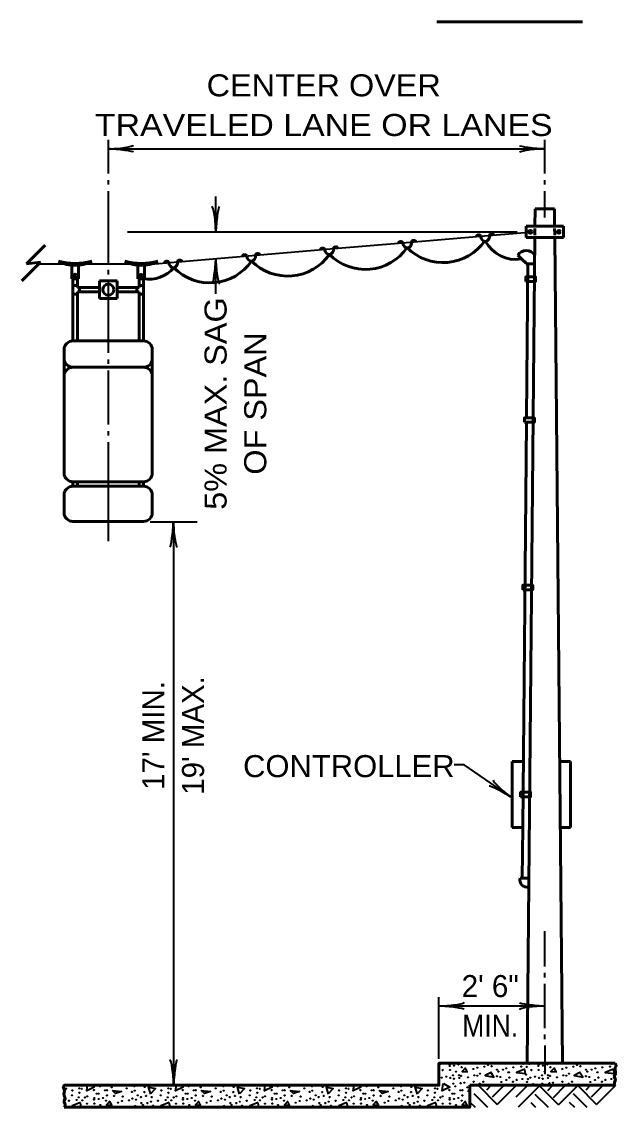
# Model space of a CAD drawing. Extents: x -1 to 679, y 1 to 441.
# Drawn here: x 308.1 to 375.5, y 100.6 to 223.8 of the extents above; entities that cross this region are included whole.
import ezdxf
from ezdxf.enums import TextEntityAlignment as Align

# ---------------------------------------------------------------- set-up
doc = ezdxf.new("R2010")
doc.units = 0
doc.layers.add('1', color=7, linetype='Continuous', lineweight=35)

msp = doc.modelspace()

# ---------------------------------------------------------------- hatches: boundary and pattern name
at = {"layer": '1'}
for points in [[(365.932, 199.947, 1), (365.608, 199.947, 1)], [(369.173, 199.947, 1), (368.85, 199.947, 1)], [(314.264, 194.997, 1), (314.014, 194.997, 1)], [(321.766, 194.994, 1), (321.516, 194.994, 1)]]:
    msp.add_hatch(color=256, dxfattribs=at).paths.add_polyline_path(points)

# ---------------------------------------------------------------- linework, layer by layer
at = {"layer": '1', "lineweight": 53}
for p, q in [((371.671, 223.796), (355.171, 223.796)), ((366.303, 202.57), (366.285, 200.57)), ((366.304, 202.57), (368.507, 202.57)), ((368.507, 202.57), (368.526, 200.57)), ((365.285, 200.57), (369.526, 200.57)), ((365.285, 200.57), (365.285, 199.32)), ((366.283, 200.32), (366.276, 199.57)), ((368.528, 200.32), (368.535, 199.57)), ((369.526, 200.57), (369.526, 199.32)), ((308.617, 196.302), (310.739, 198.423)), ((365.285, 199.32), (369.526, 199.32)), ((366.273, 199.32), (365.405, 105.57)), ((368.537, 199.32), (369.406, 105.57)), ((365.056, 196.578), (364.349, 197.285)), ((308.084, 194.376), (310.206, 196.497)), ((308.617, 196.302), (310.206, 196.497)), ((313.767, 194.619), (313.767, 196.119)), ((314.517, 194.619), (314.517, 196.119)), ((321.267, 194.619), (321.267, 196.119)), ((322.017, 194.619), (322.017, 196.119)), ((366.246, 196.32), (365.246, 196.32)), ((365.496, 196.32), (365.333, 178.827)), ((313.767, 194.619), (314.517, 194.619)), ((313.892, 194.619), (313.892, 187.57)), ((314.392, 193.869), (313.892, 193.869)), ((314.392, 193.619), (314.392, 194.619)), ((316.892, 193.619), (314.392, 193.619)), ((314.642, 193.619), (314.642, 193.119)), ((316.892, 194.369), (318.892, 194.369)), ((316.892, 194.369), (316.892, 192.369)), ((318.892, 194.369), (318.892, 192.369)), ((318.892, 193.619), (321.392, 193.619)), ((321.142, 193.619), (321.142, 193.119)), ((321.267, 194.619), (322.017, 194.619)), ((321.392, 193.619), (321.392, 194.619)), ((321.392, 193.869), (321.892, 193.869)), ((321.892, 194.619), (321.892, 187.57)), ((314.392, 192.869), (313.892, 192.869)), ((316.892, 193.119), (314.392, 193.119)), ((314.392, 193.119), (314.392, 187.57)), ((316.892, 192.369), (318.892, 192.369)), ((318.892, 193.119), (321.392, 193.119)), ((321.392, 193.119), (321.392, 187.57)), ((321.392, 192.869), (321.892, 192.869)), ((313.892, 187.57), (321.892, 187.57)), ((312.892, 186.57), (312.892, 172.57)), ((322.892, 186.57), (322.892, 172.57)), ((313.892, 184.57), (321.892, 184.57)), ((365.329, 178.321), (364.903, 132.329)), ((313.892, 171.57), (321.892, 171.57)), ((313.892, 171.57), (313.892, 171.07)), ((314.392, 171.57), (314.392, 171.07)), ((321.392, 171.57), (321.392, 171.07)), ((321.892, 171.57), (321.892, 171.07)), ((312.892, 170.07), (312.892, 168.07)), ((313.892, 171.07), (321.892, 171.07)), ((322.892, 170.07), (322.892, 168.07)), ((313.892, 167.07), (321.892, 167.07)), ((363.722, 139.823), (363.722, 132.329)), ((364.972, 139.823), (363.722, 139.823)), ((370.338, 139.823), (369.088, 139.823)), ((370.338, 139.823), (370.338, 132.329)), ((364.903, 132.329), (363.722, 132.329)), ((364.903, 132.329), (364.85, 126.569)), ((370.338, 132.329), (369.158, 132.329)), ((365.6, 126.569), (364.6, 126.569)), ((375.405, 103.07), (358.905, 103.07))]:
    msp.add_line(p, q, dxfattribs=at)
at = {"layer": '1'}
for p, q in [((317.892, 210.369), (317.892, 206.57)), ((367.405, 206.57), (367.405, 210.369)), ((317.892, 209.369), (367.405, 209.369)), ((317.892, 205.82), (317.892, 205.32)), ((367.405, 205.32), (367.405, 205.82)), ((317.892, 204.57), (317.892, 196.369)), ((367.405, 201.57), (367.405, 204.57)), ((330.094, 199.945), (330.094, 203.945)), ((320.094, 199.945), (364.285, 199.945)), ((359.645, 199.399), (365.615, 199.902)), ((343.949, 198.075), (350.801, 198.653)), ((350.798, 198.653), (359.645, 199.398)), ((326.254, 196.584), (335.1, 197.33)), ((335.1, 197.33), (343.949, 198.076)), ((313.018, 196.29), (309.999, 196.29)), ((320.518, 196.29), (315.265, 196.29)), ((322.764, 196.29), (326.254, 196.584)), ((330.094, 192.908), (330.094, 196.908)), ((317.892, 195.619), (317.892, 195.119)), ((317.892, 191.369), (317.892, 186.22)), ((317.892, 185.47), (317.892, 184.97)), ((317.892, 184.22), (317.892, 179.07)), ((317.892, 179.07), (317.892, 178.07)), ((317.892, 177.32), (317.892, 176.82)), ((317.892, 176.07), (317.892, 164.815)), ((322.642, 167.032), (327.995, 167.032)), ((325.3, 167.032), (325.3, 103.07)), ((367.405, 116.57), (367.405, 120.57)), ((367.405, 115.32), (367.405, 115.82)), ((367.405, 109.57), (367.405, 114.57)), ((355.405, 106.07), (355.405, 113.07)), ((355.405, 112.07), (367.405, 112.07)), ((367.405, 108.32), (367.405, 108.82)), ((367.405, 107.57), (367.405, 104.32)), ((358.693, 102.487), (358.905, 102.462)), ((358.905, 102.274), (358.693, 102.487)), ((359.885, 103.031), (362.025, 100.891)), ((361.305, 103.031), (360.786, 102.51)), ((362.745, 103.031), (361.425, 101.71)), ((364.166, 103.031), (362.025, 100.891)), ((365.445, 103.031), (364.125, 101.71)), ((366.865, 103.031), (364.405, 100.57)), ((365.942, 103.07), (365.973, 103.287)), ((366.013, 103.267), (366.356, 103.07)), ((366.765, 103.031), (368.965, 100.831)), ((368.286, 103.031), (367.726, 102.45)), ((369.726, 103.031), (368.346, 101.65)), ((371.145, 103.031), (368.965, 100.831)), ((371.145, 103.031), (373.286, 100.891)), ((372.565, 103.031), (372.046, 102.51)), ((374.005, 103.031), (372.685, 101.71)), ((375.425, 103.031), (373.286, 100.891)), ((358.905, 101.17), (359.505, 100.57)), ((359.365, 102.13), (360.925, 100.57)), ((365.825, 101.111), (366.365, 100.57)), ((366.286, 102.07), (367.802, 100.57)), ((370.166, 101.17), (370.765, 100.57)), ((370.625, 102.13), (372.185, 100.57)), ((320.993, 100.727), (320.707, 100.57)), ((321.066, 100.57), (320.953, 100.747)), ((331.073, 100.727), (330.787, 100.57)), ((331.146, 100.57), (331.033, 100.747)), ((341.153, 100.727), (340.867, 100.57)), ((341.226, 100.57), (341.113, 100.747)), ((351.233, 100.727), (350.947, 100.57)), ((351.306, 100.57), (351.193, 100.747))]:
    msp.add_line(p, q, dxfattribs=at)
at = {"layer": '1', "lineweight": 53}
for points in [[(365.246, 194.32), (365.246, 194.82), (366.371, 194.82), (366.371, 194.32)], [(365.102, 178.327), (365.102, 178.827), (366.227, 178.827), (366.227, 178.327)], [(364.911, 159.322), (364.911, 159.822), (366.036, 159.822), (366.036, 159.322)], [(364.669, 135.823), (364.669, 136.323), (365.794, 136.323), (365.794, 135.823)]]:
    msp.add_lwpolyline(points, close=True, dxfattribs=at)
at = {"layer": '1'}
for points in [[(317.892, 194.369), (317.892, 191.869), (317.892, 191.369)], [(363.703, 135.714), (358.28, 139.432), (357.127, 139.432)], [(358.413, 105.047), (358.033, 104.647), (358.613, 104.607), (358.413, 105.007)], [(365.133, 104.907), (364.193, 104.527), (365.233, 104.407), (365.133, 104.867)], [(368.493, 105.047), (368.113, 104.647), (368.693, 104.607), (368.493, 105.007)], [(375.213, 104.907), (374.273, 104.527), (375.313, 104.407), (375.213, 104.867)], [(361.313, 104.527), (360.653, 104.167), (361.633, 103.987), (361.273, 104.547)], [(371.393, 104.527), (370.733, 104.167), (371.713, 103.987), (371.353, 104.547)], [(312.795, 102.784), (313.173, 102.707), (312.923, 102.439)], [(315.957, 103.07), (316.313, 102.867), (315.453, 102.447), (315.542, 103.07)], [(322.713, 102.067), (322.473, 102.867), (323.253, 102.707), (322.693, 102.107)], [(326.036, 103.07), (326.393, 102.867), (325.533, 102.447), (325.622, 103.07)], [(332.793, 102.067), (332.553, 102.867), (333.333, 102.707), (332.773, 102.107)], [(336.116, 103.07), (336.473, 102.867), (335.613, 102.447), (335.702, 103.07)], [(342.873, 102.067), (342.633, 102.867), (343.413, 102.707), (342.853, 102.107)], [(346.197, 103.07), (346.553, 102.867), (345.693, 102.447), (345.782, 103.07)], [(352.953, 102.067), (352.713, 102.867), (353.493, 102.707), (352.933, 102.107)], [(355.933, 103.267), (356.633, 102.867), (355.773, 102.447), (355.893, 103.287)], [(314.733, 101.107), (313.793, 100.727), (314.833, 100.607), (314.733, 101.067)], [(318.093, 101.247), (317.713, 100.847), (318.293, 100.807), (318.093, 101.207)], [(324.813, 101.107), (323.873, 100.727), (324.913, 100.607), (324.813, 101.067)], [(328.173, 101.247), (327.793, 100.847), (328.373, 100.807), (328.173, 101.207)], [(334.893, 101.107), (333.953, 100.727), (334.993, 100.607), (334.893, 101.067)], [(338.253, 101.247), (337.873, 100.847), (338.453, 100.807), (338.253, 101.207)], [(344.973, 101.107), (344.033, 100.727), (345.073, 100.607), (344.973, 101.067)], [(348.333, 101.247), (347.953, 100.847), (348.533, 100.807), (348.333, 101.207)], [(355.053, 101.107), (354.113, 100.727), (355.153, 100.607), (355.053, 101.067)], [(358.413, 101.247), (358.033, 100.847), (358.613, 100.807), (358.413, 101.207)]]:
    msp.add_lwpolyline(points, dxfattribs=at)
at = {"layer": '1', "lineweight": 53}
for points in [[(312.906, 100.57), (312.996, 100.702), (313.002, 100.915), (312.893, 101.16), (312.909, 101.302), (313.024, 101.575), (312.898, 101.918), (312.871, 102.076), (312.925, 102.414), (312.909, 102.573), (312.795, 102.785), (312.906, 103.07), (355.405, 103.07), (355.405, 105.57), (375.405, 105.57)], [(375.405, 105.57), (375.516, 105.285), (375.402, 105.073), (375.385, 104.914), (375.44, 104.576), (375.413, 104.418), (375.287, 104.075), (375.402, 103.802), (375.418, 103.66), (375.309, 103.415), (375.315, 103.202), (375.405, 103.07)], [(358.905, 103.07), (358.905, 100.57), (312.906, 100.57)]]:
    msp.add_lwpolyline(points, dxfattribs=at)
at = {"layer": '1'}
for points in [[(318.373, 102.487), (319.413, 102.367), (318.733, 102.127)], [(328.453, 102.487), (329.493, 102.367), (328.813, 102.127)], [(338.533, 102.487), (339.573, 102.367), (338.893, 102.127)], [(348.613, 102.487), (349.653, 102.367), (348.973, 102.127)]]:
    msp.add_lwpolyline(points, close=True, dxfattribs=at)
at = {"layer": '1', "lineweight": 53}
for centre, radius in [((365.77, 199.947), 0.162), ((369.012, 199.947), 0.162), ((314.139, 194.997), 0.125), ((321.641, 194.994), 0.125), ((317.903, 193.379), 0.625)]:
    msp.add_circle(centre, radius, dxfattribs=at)
at = {"layer": '1'}
for centre in [(355.566, 105.484), (355.817, 104.786), (356.613, 105.25), (356.626, 105.417), (356.652, 104.799), (357.116, 105.303), (357.607, 105.431), (357.972, 105.117), (359.311, 104.905), (359.761, 105.077), (360.57, 105.17), (360.967, 105.364), (361.365, 105.237), (361.921, 105.523), (361.988, 104.839), (362.664, 104.839), (363.061, 104.998), (363.154, 105.523), (363.843, 105.104), (364.731, 105.197), (364.943, 105.51), (365.367, 105.157), (365.646, 105.484), (365.897, 104.786), (366.693, 105.25), (366.706, 105.417), (366.732, 104.799), (367.196, 105.303), (367.687, 105.431), (368.052, 105.117), (369.391, 104.905), (369.841, 105.077), (370.65, 105.17), (371.047, 105.364), (371.445, 105.237), (372.001, 105.523), (372.068, 104.839), (372.744, 104.839), (373.141, 104.998), (373.234, 105.523), (373.923, 105.104), (374.811, 105.197), (375.023, 105.51), (355.698, 103.937), (356.228, 104.057), (356.679, 103.911), (356.997, 104.202), (357.103, 103.805), (357.328, 104.613), (357.686, 104.216), (357.699, 103.898), (357.919, 104.136), (358.701, 103.964), (359.417, 104.189), (359.761, 104.149), (360.079, 104.388), (361.988, 104.096), (362.147, 104.627), (362.372, 104.004), (363.035, 103.672), (363.287, 104.534), (363.34, 104.534), (363.406, 103.951), (364.214, 103.685), (364.864, 103.778), (365.261, 104.269), (365.5, 103.765), (365.778, 103.937), (366.308, 104.057), (366.759, 103.911), (367.077, 104.202), (367.183, 103.805), (367.408, 104.613), (367.766, 104.216), (367.779, 103.898), (367.999, 104.136), (368.781, 103.964), (369.497, 104.189), (369.841, 104.149), (370.159, 104.388), (372.068, 104.096), (372.227, 104.627), (372.452, 104.004), (373.115, 103.672), (373.367, 104.534), (373.42, 104.534), (373.486, 103.951), (374.294, 103.685), (374.944, 103.778), (313.841, 102.479), (314.623, 102.731), (314.914, 102.665), (316.266, 102.519), (316.955, 102.956), (317.519, 102.49), (317.745, 102.506), (318.288, 102.837), (319.985, 102.731), (320.581, 102.32), (320.859, 102.956), (320.899, 102.466), (321.999, 102.293), (322.039, 102.89), (323.921, 102.479), (324.703, 102.731), (324.994, 102.665), (326.346, 102.519), (327.035, 102.956), (327.599, 102.49), (327.825, 102.506), (328.368, 102.837), (330.065, 102.731), (330.661, 102.32), (330.939, 102.956), (330.979, 102.466), (332.079, 102.293), (332.119, 102.89), (334.001, 102.479), (334.783, 102.731), (335.074, 102.665), (336.426, 102.519), (337.115, 102.956), (337.679, 102.49), (337.905, 102.506), (338.448, 102.837), (340.145, 102.731), (340.741, 102.32), (341.019, 102.956), (341.059, 102.466), (342.159, 102.293), (342.199, 102.89), (344.081, 102.479), (344.863, 102.731), (345.154, 102.665), (346.506, 102.519), (347.195, 102.956), (347.759, 102.49), (347.985, 102.506), (348.528, 102.837), (350.225, 102.731), (350.821, 102.32), (351.099, 102.956), (351.139, 102.466), (352.239, 102.293), (352.279, 102.89), (354.161, 102.479), (354.943, 102.731), (355.234, 102.665), (356.586, 102.519), (357.05, 103.248), (357.275, 102.956), (357.839, 102.49), (357.858, 103.301), (358.065, 102.506), (358.277, 103.354), (358.608, 102.837), (359.337, 103.46), (360.026, 103.248), (360.424, 103.46), (361.59, 103.129), (362.491, 103.434), (363.803, 103.46), (365.327, 103.142), (365.394, 103.447), (367.13, 103.248), (367.938, 103.301), (368.357, 103.354), (369.417, 103.46), (370.106, 103.248), (370.504, 103.46), (371.67, 103.129), (372.571, 103.434), (373.883, 103.46), (313.443, 101.304), (313.774, 101.935), (314.331, 101.397), (314.543, 101.71), (314.636, 102.214), (314.967, 101.357), (315.246, 101.684), (315.524, 101.803), (316.293, 101.45), (316.306, 101.617), (316.597, 102.121), (316.796, 101.503), (316.823, 102.121), (317.287, 101.631), (317.652, 101.317), (317.745, 101.909), (318.553, 101.869), (318.991, 101.105), (319.441, 101.277), (319.547, 101.79), (320.25, 101.37), (320.647, 101.564), (321.045, 101.437), (321.244, 101.922), (321.601, 101.723), (321.668, 101.039), (322.185, 101.869), (322.344, 101.039), (322.741, 101.198), (322.834, 101.723), (323.523, 101.304), (323.854, 101.935), (324.411, 101.397), (324.623, 101.71), (324.716, 102.214), (325.047, 101.357), (325.326, 101.684), (325.604, 101.803), (326.373, 101.45), (326.386, 101.617), (326.677, 102.121), (326.876, 101.503), (326.903, 102.121), (327.367, 101.631), (327.732, 101.317), (327.825, 101.909), (328.633, 101.869), (329.071, 101.105), (329.521, 101.277), (329.627, 101.79), (330.33, 101.37), (330.727, 101.564), (331.125, 101.437), (331.324, 101.922), (331.681, 101.723), (331.748, 101.039), (332.265, 101.869), (332.424, 101.039), (332.821, 101.198), (332.914, 101.723), (333.603, 101.304), (333.934, 101.935), (334.491, 101.397), (334.703, 101.71), (334.796, 102.214), (335.127, 101.357), (335.406, 101.684), (335.684, 101.803), (336.453, 101.45), (336.466, 101.617), (336.757, 102.121), (336.956, 101.503), (336.983, 102.121), (337.447, 101.631), (337.812, 101.317), (337.905, 101.909), (338.713, 101.869), (339.151, 101.105), (339.601, 101.277), (339.707, 101.79), (340.41, 101.37), (340.807, 101.564), (341.205, 101.437), (341.404, 101.922), (341.761, 101.723), (341.828, 101.039), (342.345, 101.869), (342.504, 101.039), (342.901, 101.198), (342.994, 101.723), (343.683, 101.304), (344.014, 101.935), (344.571, 101.397), (344.783, 101.71), (344.876, 102.214), (345.207, 101.357), (345.486, 101.684), (345.764, 101.803), (346.533, 101.45), (346.546, 101.617), (346.837, 102.121), (347.036, 101.503), (347.063, 102.121), (347.527, 101.631), (347.892, 101.317), (347.985, 101.909), (348.793, 101.869), (349.231, 101.105), (349.681, 101.277), (349.787, 101.79), (350.49, 101.37), (350.887, 101.564), (351.285, 101.437), (351.484, 101.922), (351.841, 101.723), (351.908, 101.039), (352.425, 101.869), (352.584, 101.039), (352.981, 101.198), (353.074, 101.723), (353.763, 101.304), (354.094, 101.935), (354.651, 101.397), (354.863, 101.71), (354.956, 102.214), (355.287, 101.357), (355.566, 101.684), (355.844, 101.803), (356.613, 101.45), (356.626, 101.617), (356.917, 102.121), (357.116, 101.503), (357.143, 102.121), (357.607, 101.631), (357.972, 101.317), (358.065, 101.909), (358.873, 101.869), (315.497, 100.986), (316.332, 100.999), (317.008, 100.813), (321.827, 100.827), (322.967, 100.734), (323.02, 100.734), (325.577, 100.986), (326.412, 100.999), (327.088, 100.813), (331.907, 100.827), (333.047, 100.734), (333.1, 100.734), (335.657, 100.986), (336.492, 100.999), (337.168, 100.813), (341.987, 100.827), (343.127, 100.734), (343.18, 100.734), (345.737, 100.986), (346.572, 100.999), (347.248, 100.813), (352.067, 100.827), (353.207, 100.734), (353.26, 100.734), (355.817, 100.986), (356.652, 100.999), (357.328, 100.813)]:
    msp.add_circle(centre, 0.0265, dxfattribs=at)
at = {"layer": '1', "lineweight": 53}
for centre, radius, start, end in [((361.397, 199.458), 0.267, 24.08975, 164.4687), ((351.056, 198.581), 0.267, 25.5313, 164.45861), ((355.885, 202.211), 5.764, 224.78783, 325.11132), ((352.55, 198.712), 0.267, 24.08975, 164.4687), ((359.903, 199.327), 0.267, 25.5313, 164.45861), ((364.057, 200.61), 3.789, 207.50003, 280.53329), ((333.362, 197.09), 0.267, 25.5313, 164.45861), ((338.247, 200.683), 5.764, 224.78783, 325.11132), ((334.857, 197.221), 0.267, 24.08975, 164.4687), ((342.211, 197.836), 0.267, 25.5313, 164.45861), ((347.066, 201.447), 5.764, 224.78783, 325.11132), ((343.705, 197.967), 0.267, 24.08975, 164.4687), ((365.311, 196.692), 1.131, 32.91213, 148.34152), ((314.142, 203.525), 7.156, 254.81071, 285.18929), ((314.142, 199.884), 3.766, 240.13717, 299.86284), ((321.642, 203.525), 7.156, 254.81071, 285.18929), ((321.642, 199.884), 3.766, 240.13717, 299.86284), ((324.516, 196.344), 0.267, 25.5313, 164.45861), ((329.428, 199.92), 5.764, 224.78783, 325.11132), ((326.011, 196.475), 0.267, 24.08975, 164.4687), ((365.047, 196.373), 0.205, 344.97633, 87.57779), ((322.502, 198.331), 3.762, 260.66909, 318.91993), ((313.892, 186.57), 1, 90, 180), ((321.892, 186.57), 1, 0, 90), ((313.892, 185.57), 1, 180, 270), ((321.892, 185.57), 1, 270, 0), ((313.892, 183.57), 1, 90, 180), ((321.892, 183.57), 1, 0, 90), ((313.892, 172.57), 1, 180, 270), ((321.892, 172.57), 1, 270, 0), ((313.892, 170.07), 1, 90, 180), ((321.892, 170.07), 1, 0, 90), ((313.892, 168.07), 1, 180, 270), ((321.892, 168.07), 1, 270, 0), ((365.396, 126.367), 0.821, 165.76102, 283.71131)]:
    msp.add_arc(centre, radius, start, end, dxfattribs=at)
at = {"layer": '1'}
for centre, start, end in [((359.867, 105.59), 226.35082, 313.64918), ((369.947, 105.59), 226.35082, 313.64918), ((375.447, 105.157), 61.61934, 241.7845), ((355.42, 103.765), 237.37076, 122.62924), ((375.341, 104.269), 32.83014, 287.06312), ((313.682, 103.089), 223.9797, 316.0203), ((314.199, 103.062), 162.01481, 17.98519), ((318.964, 103.062), 162.01481, 17.98519), ((323.762, 103.089), 223.9797, 316.0203), ((324.279, 103.062), 162.01481, 17.98519), ((329.044, 103.062), 162.01481, 17.98519), ((333.842, 103.089), 223.9797, 316.0203), ((334.359, 103.062), 162.01481, 17.98519), ((339.124, 103.062), 162.01481, 17.98519), ((343.922, 103.089), 223.9797, 316.0203), ((344.439, 103.062), 162.01481, 17.98519), ((349.204, 103.062), 162.01481, 17.98519), ((354.002, 103.089), 223.9797, 316.0203), ((354.519, 103.062), 162.01481, 17.98519), ((359.284, 103.062), 17.98519, 162.01481), ((364.082, 103.089), 316.0203, 223.9797), ((364.599, 103.062), 17.98519, 162.01481), ((369.364, 103.062), 17.98519, 162.01481), ((374.162, 103.089), 316.0203, 223.9797), ((374.679, 103.062), 17.98519, 162.01481), ((319.759, 100.588), 318.30023, 221.69977), ((329.839, 100.588), 318.30023, 221.69977), ((339.919, 100.588), 318.30023, 221.69977), ((349.999, 100.588), 318.30023, 221.69977)]:
    msp.add_arc(centre, 0.0265, start, end, dxfattribs=at)
at = {"layer": '1', "lineweight": 40}
for centre, major_axis, ratio, start_param, end_param in [((318.992, 209.637), (-1.786, -0.156), 0.122415, 0.8963533, 3.1415927), ((366.285, 209.58), (1.756, -0.176), 0.07063, 3.1407148, 5.41811), ((319.021, 209.149), (-1.756, 0.176), 0.07063, 3.1407148, 5.41811), ((366.314, 209.092), (1.786, 0.156), 0.122415, 0.8963533, 3.1415927), ((329.818, 201.036), (0.156, -1.786), 0.122415, 0.8963533, 3.1415927), ((329.818, 201.036), (0.156, -1.786), 0.122415, 0.8963533, 3.1415927), ((330.306, 201.065), (-0.176, -1.756), 0.07063, 3.1407148, 5.41811), ((330.306, 201.065), (-0.176, -1.756), 0.07063, 3.1407148, 5.41811), ((329.883, 195.787), (0.176, 1.756), 0.07063, 3.1407148, 5.41811), ((329.883, 195.787), (0.176, 1.756), 0.07063, 3.1407148, 5.41811), ((330.371, 195.817), (-0.156, 1.786), 0.122415, 0.8963533, 3.1415927), ((330.371, 195.817), (-0.156, 1.786), 0.122415, 0.8963533, 3.1415927), ((325.08, 165.902), (0.176, 1.756), 0.07063, 3.1407148, 5.41811), ((325.568, 165.932), (-0.156, 1.786), 0.122415, 0.8963533, 3.1415927), ((362.648, 136.172), (-1.548, 0.848), 0.07063, 4.006668, 6.2840632), ((362.948, 136.558), (1.384, -1.139), 0.122415, 3.1415927, 5.386832), ((356.497, 112.347), (-1.786, -0.156), 0.122415, 0.8963533, 3.1415927), ((356.497, 112.347), (-1.786, -0.156), 0.122415, 0.8963533, 3.1415927), ((366.285, 112.282), (1.756, -0.176), 0.07063, 3.1407148, 5.41811), ((356.526, 111.859), (-1.756, 0.176), 0.07063, 3.1407148, 5.41811), ((356.526, 111.859), (-1.756, 0.176), 0.07063, 3.1407148, 5.41811), ((366.314, 111.794), (1.786, 0.156), 0.122415, 0.8963533, 3.1415927), ((325.032, 104.171), (0.156, -1.786), 0.122415, 0.8963533, 3.1415927), ((325.52, 104.2), (-0.176, -1.756), 0.07063, 3.1407148, 5.41811)]:
    msp.add_ellipse(centre, major_axis=major_axis, ratio=ratio, start_param=start_param, end_param=end_param, dxfattribs=at)
at = {"layer": '1', "lineweight": 53}
for centre in [(351.795, 198.74), (360.642, 199.486), (334.101, 197.249), (342.95, 197.995), (325.255, 196.503)]:
    msp.add_ellipse(centre, major_axis=(0.055, -0.626), ratio=0.795507, start_param=4.712389, end_param=7.8539816, dxfattribs=at)

# ---------------------------------------------------------------- texts
at = {"layer": '1'}
for s, width, p in [('CENTER OVER', 1.1, (342.339, 215.325)), ('TRAVELED LANE OR LANES', 1.15, (342.339, 210.825)), ('MIN.', 0.9, (361.22, 108.575))]:
    msp.add_text(s, height=2.5, dxfattribs=dict(at, width=width)).set_placement(p, align=Align.CENTER)
at = {"layer": '1', "width": 1.1}
for s, p in [('5% MAX. SAG', (331.32, 180.45)), ('OF SPAN', (335.82, 180.45))]:
    msp.add_text(s, height=2.5, rotation=90, dxfattribs=at).set_placement(p, align=Align.CENTER)
at = {"layer": '1'}
for s, p in [("19' MAX.", (328.762, 142.777)), ("17' MIN.", (324.262, 142.778))]:
    msp.add_text(s, height=2.5, rotation=90, dxfattribs=at).set_placement(p, align=Align.CENTER)
at = {"layer": '1', "width": 1.05}
msp.add_text('CONTROLLER', height=2.5, dxfattribs=at).set_placement((333.19, 138.047))
at = {"layer": '1'}
msp.add_text('2\' 6"', height=2.5, dxfattribs=at).set_placement((361.22, 113.075), align=Align.CENTER)

doc.saveas('drawing.dxf')
